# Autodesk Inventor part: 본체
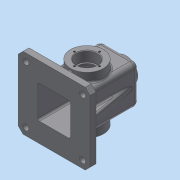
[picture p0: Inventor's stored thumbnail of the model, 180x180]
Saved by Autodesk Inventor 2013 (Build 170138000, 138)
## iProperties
Created: 2018-10
Part Number: 본체
Material: 일반
Document SubType Name: Modeling
Designer: Administrator
Density: 1 g/cm^3
Author: Administrator
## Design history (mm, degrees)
sketch "스케치1"
  geometry: L1 (-32.5, -32.5)-(32.5, -32.5); L2 (32.5, -32.5)-(32.5, 32.5); L3 (32.5, 32.5)-(-32.5, 32.5); L4 (-32.5, 32.5)-(-32.5, -32.5); L5 (-32.5, -32.5)-(32.5, 32.5); L6 (32.5, -32.5)-(-32.5, 32.5); 1 further point
  constraints: 12 end point, 2 midpoint, 2 parallel, 1 horizontal, 1 perpendicular
  dimensions: "d0" = 65 distance of L3.end L2.end; "d1" = 65 distance of L2.end L1.end
extrude "돌출1" new body sketch "스케치1" stored distance "d2" = 110; taper "d3" = 0 deg
sketch "스케치2"
  geometry: L1 (27.5, 27.5)-(-27.5, 27.5); L2 (-27.5, 27.5)-(-27.5, -27.5); L3 (-27.5, -27.5)-(27.5, -27.5); L4 (27.5, -27.5)-(27.5, 27.5); L5 (27.5, 27.5)-(-27.5, -27.5); L6 (-27.5, 27.5)-(27.5, -27.5); 1 further point
  constraints: 12 end point, 2 midpoint, 2 parallel, 1 horizontal, 1 perpendicular
  dimensions: "d4" = 55 distance of L3.end L2.end; "d5" = 55 distance of L2.end L1.end
extrude "돌출2" cut sketch "스케치2" distance "d6" = 105; taper "d7" = 0 deg
sketch "스케치3"
  geometry: C1 r 17.5 at (32.5, -55); C2 r 27.5 at (32.5, -55); 1 further point
  constraints: 2 centre point, 2 coincident
  dimensions: "d8" = 35 diameter of C1; "d9" = 55 diameter of C2
extrude "돌출3" join sketch "스케치3" distance "d10" = 15; taper "d11" = 0 deg
sketch "스케치4"
  geometry: C1 r 17.5 at (32.5, -55); C2 r 27.5 at (32.5, -55); 1 further point
  constraints: 2 centre point, 2 coincident
  dimensions: "d12" = 35 diameter of C1; "d13" = 55 diameter of C2
extrude "돌출4" join sketch "스케치4" distance "d14" = 15; taper "d15" = 0 deg
sketch "스케치5"
  geometry: C1 r 17.5 at (0, 0) reference; C2 r 27.5 at (0, 0) reference; C3 r 17.5 at (0, 0)
  constraints: 1 centre point, 1 coincident
  dimensions: "d16" = 35 diameter of C3
extrude "돌출5" cut sketch "스케치5" distance "d17" = 17; taper "d18" = 0 deg
sketch "스케치6"
  geometry: C1 r 17.5 at (0, 0) reference; C2 r 27.5 at (0, 0) reference; C3 r 17.5 at (0, 0)
  constraints: 1 centre point, 1 coincident
  dimensions: "d19" = 35 diameter of C3
extrude "돌출6" cut sketch "스케치6" distance "d20" = 17; taper "d21" = 0 deg
sketch "스케치7"
  geometry: C1 r 17.5 at (0, 0) reference; C2 r 15 at (0, 0)
  constraints: 1 centre point, 1 coincident
  dimensions: "d22" = 30 diameter of C2
extrude "돌출7" cut sketch "스케치7" stored distance "d23" = 17; taper "d24" = 0 deg
sketch "스케치8"
  geometry: C1 r 20 at (0, 0); 1 further point
  constraints: 1 centre point, 1 coincident
  dimensions: "d25" = 40 diameter of C1
extrude "돌출8" join sketch "스케치8" distance "d26" = 10; taper "d27" = 0 deg
sketch "스케치9"
  geometry: C1 r 20 at (0, 0) reference; 1 further point
  constraints: 1 coincident
hole "구멍1" sketch "스케치9" at (0, 0) diameter "d28" = 22.835; stored, may be unused: countersink angle "d32" = 90 deg, drill point angle "d34" = 118 deg; dims "d29" = 6, "d30" = 4, "d31" = 2, "d33" = 8
sketch "스케치10"
  geometry: L1 (-32.5, -32.5)-(32.5, -32.5) reference; L2 (32.5, -32.5)-(32.5, 32.5) reference; L3 (32.5, 32.5)-(-32.5, 32.5) reference; L4 (-32.5, 32.5)-(-32.5, -32.5) reference; L5 (60, 60)-(-60, 60); L6 (-60, 60)-(-60, -60); L7 (-60, -60)-(60, -60); L8 (60, -60)-(60, 60); L9 (60, 60)-(-60, -60); L10 (-60, 60)-(60, -60); 1 further point
  constraints: 12 end point, 2 midpoint, 2 parallel, 1 horizontal, 1 perpendicular
  dimensions: "d35" = 120 distance of L7.end L6.end; "d36" = 120 distance of L6.end L5.end
extrude "돌출9" join sketch "스케치10" distance "d37" = 10; taper "d38" = 0 deg
chamfer "모따기1" distance "d39" = 8; stored, may be unused: second distance "d40" = 2, angle "d41" = 45 deg
sketch "스케치11"
  geometry: L1 (-48, -45)-(-42.093, -11.501); L2 (-60, -55)-(-60, -45) reference; L3 (52, -45)-(-52, -45) reference; 1 further point
  constraints: 2 end point, 1 point on line
  dimensions: "d42" = 10 deg angle of L1 L2; "d43" = 12 distance from line of L1.start L2
feature "리브1" sketch "스케치11" dims "d44" = 1, "d45" = 10, "d46" = 0, "d47" = 0, "d48" = 1, "d49" = 1
fillet "모깎기1" dims "d50" = 3
fillet "모깎기2" dims "d51" = 3
fillet "모깎기3" dims "d52" = 8
fillet "모깎기4" dims "d53" = 8
fillet "모깎기5" dims "d54" = 3
fillet "모깎기6" dims "d55" = 3
fillet "모깎기7" dims "d56" = 3
fillet "모깎기8" dims "d57" = 3
sketch "스케치12"
  geometry: L1 (-42.975, 42.5)-(-31.831, 42.5); L2 (47, 27.5)-(-55, 27.5) reference; 1 further point
  constraints: 2 end point, 1 horizontal
  dimensions: "d58" = 15 distance between parallel lines of L2 L1
feature "리브2" sketch "스케치12" dims "d59" = 1, "d60" = 6, "d61" = 0, "d62" = 0, "d63" = 1, "d64" = 1
sketch "스케치14"
  geometry: L1 (0, 0)-(0, 21); C1 r 17.5 at (0, 0) reference; 1 further point
  constraints: 2 end point, 1 coincident, 1 vertical
  dimensions: "d65" = 21 distance of L1.start L1.end
hole "구멍2" sketch "스케치14" at (0, 21) diameter "d66" = 3.242; stored, may be unused: countersink angle "d70" = 90 deg, drill point angle "d72" = 118 deg; dims "d67" = 8, "d68" = 4, "d69" = 2, "d71" = 10
chamfer "모따기2" distance "d77" = 1; stored, may be unused: second distance "d78" = 2, angle "d79" = 45 deg
fillet "모깎기10" dims "d80" = 0.3
chamfer "모따기3" distance "d81" = 1; stored, may be unused: second distance "d82" = 2, angle "d83" = 45 deg
fillet "모깎기11" dims "d84" = 3
fillet "모깎기12" dims "d85" = 3
fillet "모깎기13" dims "d86" = 3
fillet "모깎기14" dims "d87" = 1
fillet "모깎기15" dims "d88" = 3
sketch "스케치15"
  geometry: L1 (47.5, 47.5)-(-47.5, 47.5); L2 (-47.5, 47.5)-(-47.5, -47.5); L3 (-47.5, -47.5)-(47.5, -47.5); L4 (47.5, -47.5)-(47.5, 47.5); L5 (47.5, 47.5)-(-47.5, -47.5); L6 (-47.5, 47.5)-(47.5, -47.5); C1 r 5 at (-47.5, -47.5); 1 further point
  constraints: 12 end point, 2 midpoint, 2 parallel, 1 centre point, 1 coincident, 1 horizontal, 1 perpendicular
  dimensions: "d89" = 95 distance of L3.end L2.end; "d90" = 95 distance of L2.end L1.end; "d91" = 10 diameter of C1
extrude "돌출10" cut sketch "스케치15" stored distance "d92" = 10; taper "d93" = 0 deg
sketch "스케치16"
  geometry: L1 (84.5, -102)-(-35.5, -102) reference; L2 (-35.5, -102)-(-35.5, -92) reference; L3 (-35.5, -92)-(-4.123, -92) reference; L4 (18.5, -91)-(0, -91) reference; L5 (18.5, -76.904)-(18.5, -91) reference; L6 (30.5, -91)-(30.5, -76.904) reference; L7 (49, -91)-(30.5, -91) reference; L8 (53.123, -92)-(84.5, -92) reference; L9 (84.5, -92)-(84.5, -102) reference; L10 (0, -65.166)-(0, -91) reference; L11 (0, 0)-(0, -28.834) reference; L12 (0, 0)-(49, 0) reference; L13 (49, -28.834)-(49, 0) reference; L14 (49, -91)-(49, -65.166) reference; L15 (-8, 0)-(-8, -91) reference; L16 (44.5, 18)-(4.5, 18) reference; C1 r 17.5 at (24.5, -47) reference; A1 r 30.5 centre (24.5, -47) between (0, -65.166) and (18.5, -76.904) reference; A2 r 30.5 centre (24.5, -47) between (49, -28.834) and (0, -28.834) reference; A3 r 30.5 centre (24.5, -47) between (30.5, -76.904) and (49, -65.166) reference; 1 further point
  constraints: 2 vertical alignment, 3 other
  dimensions: "d94" = 32.5 distance from line of point (24.5, -8) L15; "d95" = 26 distance from line of point (24.5, -8) L16
feature "엠보싱1" sketch "스케치16" dims "d8" = 35, "d9" = 55, "d96" = 0.5, "d97" = 0
feature "면 기울기1" dims angle "d98" = 7 deg
fillet "모깎기16" dims "d99" = 3
node "솔리드1"
mirror "대칭1"
mirror "대칭2"
pattern_circular "원형 패턴1" dims angle "d74" = 360 deg
mirror "대칭3"
mirror "대칭4"
mirror "대칭5"
node "절단 모서리 투영1"
